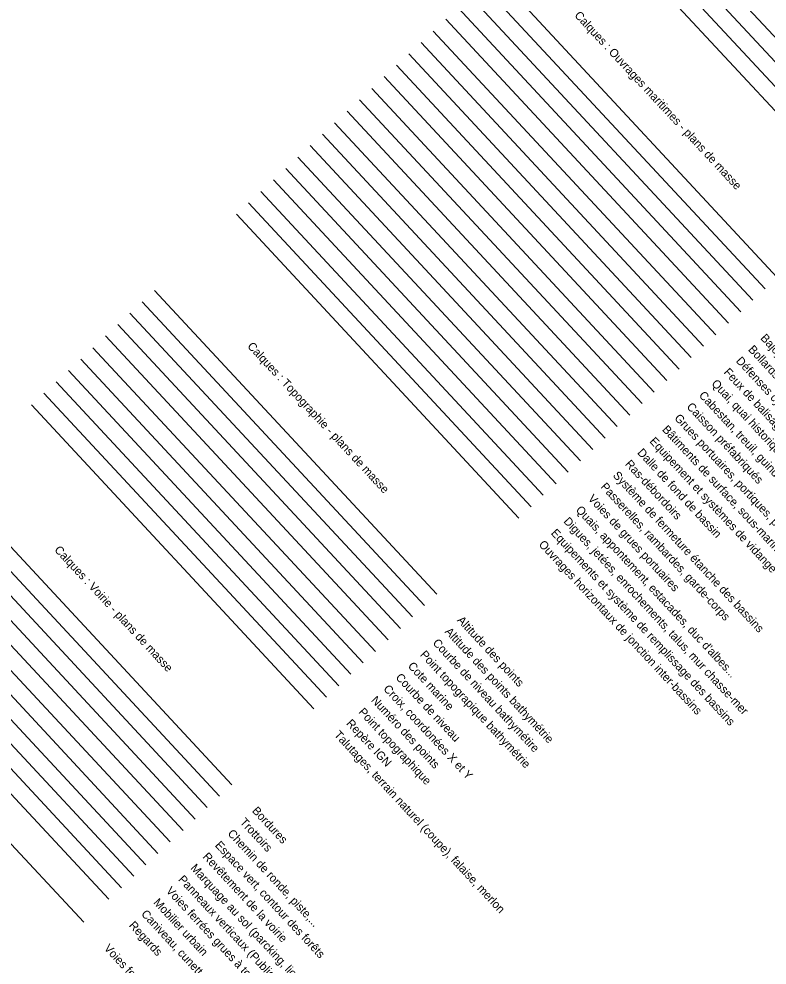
# Model space of a CAD drawing. Extents: x 704383 to 706615, y 7057567 to 7059313.
# Drawn here: x 706408.2 to 706453, y 7057621.5 to 7057678.1 of the extents above; entities that cross this region are included whole.
import ezdxf

# ---------------------------------------------------------------- set-up
doc = ezdxf.new("R2010")
doc.units = 0
for name, color, linetype in [('DH_CADRE -CARTOUCHE', 7, 'Continuous'), ('GEOSID_BATI_AERIEN _POLYGONE', 7, 'Continuous'), ('GEOSID_BATI_AERIEN_NUMERO', 7, 'Continuous'), ('GEOSID_BATI_AERIEN_PRECISION', 7, 'Continuous'), ('GEOSID_SITE_POLYGONE', 7, 'Continuous'), ('OM_BAJOYER', 7, 'Continuous'), ('OM_BATEAU PORTE', 7, 'Continuous'), ('OM_BOLLARDS', 7, 'Continuous'), ('OM_CABESTAN', 7, 'Continuous'), ('OM_CAISSON PREFA', 7, 'Continuous'), ('OM_CONSTRUCTION METAL', 7, 'Continuous'), ('OM_DEFENSE D ACCOSTAGE', 7, 'Continuous'), ('OM_EQUIP DE LEVAGE', 7, 'Continuous'), ('OM_GALERIE REFOULEMENT', 7, 'Continuous'), ('OM_NAVIRE', 7, 'Continuous'), ('OM_OUVRAGES DE PROTECTION', 7, 'Continuous'), ('OM_OUVRAGES D’ACCOSTAGE', 7, 'Continuous'), ('OM_PAL TIR LIER', 7, 'Continuous'), ('OM_PLAGEAGE', 7, 'Continuous'), ('OM_QUAI', 7, 'Continuous'), ('OM_RADIER', 7, 'Continuous'), ('OM_RAS DEBORDOIR', 7, 'Continuous'), ('OM_SIGNAL NAUTIQUE', 7, 'Continuous'), ('OM_SOUBASSEMENT', 7, 'Continuous'), ('OM_STATION DE POMPAGE', 7, 'Continuous'), ('OM_TERRE-PLEINS', 7, 'Continuous'), ('OM_VOIES DE GRUES', 7, 'Continuous'), ('TOPO_ALT POINT', 7, 'Continuous'), ('TOPO_BATHY ALT COURBE NIVEAU', 7, 'Continuous'), ('TOPO_BATHY ALT POINT', 7, 'Continuous'), ('TOPO_BATHYMETRIE', 7, 'Continuous'), ('TOPO_COTE MARINE', 7, 'Continuous'), ('TOPO_COURBE NIVEAU', 7, 'Continuous'), ('TOPO_CROIX COORDONNEE', 7, 'Continuous'), ('TOPO_NUM POINT', 7, 'Continuous'), ('TOPO_POINT', 7, 'Continuous'), ('TOPO_REPERE IGN', 7, 'Continuous'), ('TOPO_TALUS-TERRAIN', 7, 'Continuous'), ('VOIRIE BORDURE', 7, 'Continuous'), ('VOIRIE TROTTOIR', 7, 'Continuous'), ('VOIRIE_CANIVEAU_TECHNIQUE', 7, 'Continuous'), ('VOIRIE_CHEMIN', 7, 'Continuous'), ('VOIRIE_ESPACE VERT', 7, 'Continuous'), ('VOIRIE_MOBILIER_URBAIN', 7, 'Continuous'), ('VOIRIE_REGARD', 7, 'Continuous'), ('VOIRIE_ROUTE_REVETEMENT', 7, 'Continuous'), ('VOIRIE_SIGNAL HORIZON', 7, 'Continuous'), ('VOIRIE_SIGNAL VERTIC', 7, 'Continuous'), ('VOIRIE_VOIES FERREES', 7, 'Continuous'), ('VOIRIE_VOIES GRUE', 7, 'Continuous')]:
    doc.layers.add(name, color=color, linetype=linetype)

msp = doc.modelspace()

# ---------------------------------------------------------------- linework, layer by layer
at = {"layer": 'GEOSID_BATI_AERIEN _POLYGONE'}
msp.add_line((706443.786, 7057687.397), (706460.688, 7057669.229), dxfattribs=at)
at = {"layer": 'GEOSID_BATI_AERIEN_NUMERO'}
msp.add_line((706442.322, 7057686.035), (706459.234, 7057667.856), dxfattribs=at)
at = {"layer": 'GEOSID_BATI_AERIEN_PRECISION'}
msp.add_line((706443.054, 7057686.716), (706459.956, 7057668.548), dxfattribs=at)
at = {"layer": 'GEOSID_SITE_POLYGONE'}
msp.add_line((706441.589, 7057685.353), (706458.502, 7057667.175), dxfattribs=at)
at = {"layer": 'OM_BAJOYER'}
msp.add_line((706434.49, 7057678.759), (706451.402, 7057660.58), dxfattribs=at)
at = {"layer": 'OM_BATEAU PORTE'}
msp.add_line((706425.636, 7057670.522), (706442.549, 7057652.343), dxfattribs=at)
at = {"layer": 'OM_BOLLARDS'}
msp.add_line((706433.758, 7057678.077), (706450.67, 7057659.899), dxfattribs=at)
at = {"layer": 'OM_CABESTAN'}
msp.add_line((706430.806, 7057675.332), (706447.719, 7057657.153), dxfattribs=at)
at = {"layer": 'OM_CAISSON PREFA'}
msp.add_line((706430.074, 7057674.651), (706446.987, 7057656.472), dxfattribs=at)
at = {"layer": 'OM_CONSTRUCTION METAL'}
msp.add_line((706424.904, 7057669.84), (706441.806, 7057651.672), dxfattribs=at)
at = {"layer": 'OM_DEFENSE D ACCOSTAGE'}
msp.add_line((706433.003, 7057677.375), (706449.905, 7057659.207), dxfattribs=at)
at = {"layer": 'OM_EQUIP DE LEVAGE'}
msp.add_line((706429.319, 7057673.948), (706446.222, 7057655.78), dxfattribs=at)
at = {"layer": 'OM_GALERIE REFOULEMENT'}
msp.add_line((706427.855, 7057672.586), (706444.768, 7057654.407), dxfattribs=at)
at = {"layer": 'OM_NAVIRE'}
msp.add_line((706428.587, 7057673.267), (706445.5, 7057655.088), dxfattribs=at)
at = {"layer": 'OM_OUVRAGES DE PROTECTION'}
msp.add_line((706422.685, 7057667.776), (706439.587, 7057649.608), dxfattribs=at)
at = {"layer": 'OM_OUVRAGES D’ACCOSTAGE'}
msp.add_line((706423.44, 7057668.478), (706440.352, 7057650.299), dxfattribs=at)
at = {"layer": 'OM_PAL TIR LIER'}
msp.add_line((706435.222, 7057679.44), (706452.125, 7057661.272), dxfattribs=at)
at = {"layer": 'OM_PLAGEAGE'}
msp.add_line((706436.686, 7057680.802), (706453.589, 7057662.634), dxfattribs=at)
at = {"layer": 'OM_QUAI'}
msp.add_line((706431.539, 7057676.013), (706448.441, 7057657.845), dxfattribs=at)
at = {"layer": 'OM_RADIER'}
msp.add_line((706427.1, 7057671.884), (706444.003, 7057653.716), dxfattribs=at)
at = {"layer": 'OM_RAS DEBORDOIR'}
msp.add_line((706426.368, 7057671.203), (706443.281, 7057653.024), dxfattribs=at)
at = {"layer": 'OM_SIGNAL NAUTIQUE'}
msp.add_line((706432.271, 7057676.694), (706449.173, 7057658.526), dxfattribs=at)
at = {"layer": 'OM_SOUBASSEMENT'}
msp.add_line((706435.954, 7057680.121), (706452.857, 7057661.953), dxfattribs=at)
at = {"layer": 'OM_STATION DE POMPAGE'}
msp.add_line((706421.953, 7057667.095), (706438.865, 7057648.916), dxfattribs=at)
at = {"layer": 'OM_TERRE-PLEINS'}
msp.add_line((706421.22, 7057666.414), (706438.133, 7057648.235), dxfattribs=at)
at = {"layer": 'OM_VOIES DE GRUES'}
msp.add_line((706424.172, 7057669.159), (706441.084, 7057650.98), dxfattribs=at)
at = {"layer": 'TOPO_ALT POINT'}
msp.add_line((706416.317, 7057661.862), (706433.22, 7057643.694), dxfattribs=at)
at = {"layer": 'TOPO_BATHY ALT COURBE NIVEAU'}
msp.add_line((706414.853, 7057660.5), (706431.756, 7057642.332), dxfattribs=at)
at = {"layer": 'TOPO_BATHY ALT POINT'}
msp.add_line((706415.585, 7057661.181), (706432.488, 7057643.013), dxfattribs=at)
at = {"layer": 'TOPO_BATHYMETRIE'}
msp.add_line((706414.121, 7057659.819), (706431.033, 7057641.64), dxfattribs=at)
at = {"layer": 'TOPO_COTE MARINE'}
msp.add_line((706413.389, 7057659.138), (706430.301, 7057640.959), dxfattribs=at)
at = {"layer": 'TOPO_COURBE NIVEAU'}
msp.add_line((706412.634, 7057658.435), (706429.536, 7057640.267), dxfattribs=at)
at = {"layer": 'TOPO_CROIX COORDONNEE'}
msp.add_line((706411.902, 7057657.754), (706428.804, 7057639.586), dxfattribs=at)
at = {"layer": 'TOPO_NUM POINT'}
msp.add_line((706411.17, 7057657.073), (706428.072, 7057638.905), dxfattribs=at)
at = {"layer": 'TOPO_POINT'}
msp.add_line((706410.438, 7057656.392), (706427.35, 7057638.213), dxfattribs=at)
at = {"layer": 'TOPO_REPERE IGN'}
msp.add_line((706409.705, 7057655.711), (706426.618, 7057637.532), dxfattribs=at)
at = {"layer": 'TOPO_TALUS-TERRAIN'}
msp.add_line((706408.951, 7057655.008), (706425.853, 7057636.84), dxfattribs=at)
at = {"layer": 'VOIRIE BORDURE'}
msp.add_line((706404.043, 7057650.462), (706420.945, 7057632.294), dxfattribs=at)
at = {"layer": 'VOIRIE TROTTOIR'}
msp.add_line((706403.31, 7057649.781), (706420.213, 7057631.613), dxfattribs=at)
at = {"layer": 'VOIRIE_CANIVEAU_TECHNIQUE'}
msp.add_line((706397.431, 7057644.311), (706414.343, 7057626.132), dxfattribs=at)
at = {"layer": 'VOIRIE_CHEMIN'}
msp.add_line((706402.578, 7057649.1), (706419.481, 7057630.932), dxfattribs=at)
at = {"layer": 'VOIRIE_ESPACE VERT'}
msp.add_line((706401.846, 7057648.419), (706418.759, 7057630.24), dxfattribs=at)
at = {"layer": 'VOIRIE_MOBILIER_URBAIN'}
msp.add_line((706398.163, 7057644.992), (706415.075, 7057626.813), dxfattribs=at)
at = {"layer": 'VOIRIE_REGARD'}
msp.add_line((706396.676, 7057643.609), (706413.578, 7057625.441), dxfattribs=at)
at = {"layer": 'VOIRIE_ROUTE_REVETEMENT'}
msp.add_line((706401.114, 7057647.738), (706418.026, 7057629.559), dxfattribs=at)
at = {"layer": 'VOIRIE_SIGNAL HORIZON'}
msp.add_line((706400.359, 7057647.036), (706417.262, 7057628.867), dxfattribs=at)
at = {"layer": 'VOIRIE_SIGNAL VERTIC'}
msp.add_line((706399.627, 7057646.354), (706416.529, 7057628.186), dxfattribs=at)
at = {"layer": 'VOIRIE_VOIES FERREES'}
msp.add_line((706395.189, 7057642.225), (706412.081, 7057624.068), dxfattribs=at)
at = {"layer": 'VOIRIE_VOIES GRUE'}
msp.add_line((706398.895, 7057645.673), (706415.797, 7057627.505), dxfattribs=at)

# ---------------------------------------------------------------- texts
at = {"layer": 'DH_CADRE -CARTOUCHE'}
for s, p in [(' Calques : Ouvrages maritimes - plans de masse', (706441.293, 7057678.42)), (' Calques : Topographie - plans de masse', (706421.717, 7057658.628)), (' Calques : Voirie - plans de masse', (706410.169, 7057646.446))]:
    msp.add_text(s, height=0.5, rotation=312.9332, dxfattribs=at).set_placement(p)
at = {"layer": 'OM_BAJOYER'}
msp.add_text('Bajoyers de bassins, parois verticales de quai', height=0.5, rotation=312.9332, dxfattribs=at).set_placement((706452.55, 7057658.979))
at = {"layer": 'OM_BATEAU PORTE'}
msp.add_text('Système de fermeture étanche des bassins', height=0.5, rotation=312.9332, dxfattribs=at).set_placement((706443.719, 7057650.763))
at = {"layer": 'OM_BOLLARDS'}
msp.add_text('Bollards, bittes, organeaux', height=0.5, rotation=312.9332, dxfattribs=at).set_placement((706451.818, 7057658.298))
at = {"layer": 'OM_CABESTAN'}
msp.add_text('Cabestan, treuil, guindeau', height=0.5, rotation=312.9332, dxfattribs=at).set_placement((706448.866, 7057655.552))
at = {"layer": 'OM_CAISSON PREFA'}
msp.add_text('Caisson préfabriqués', height=0.5, rotation=312.9332, dxfattribs=at).set_placement((706448.134, 7057654.871))
at = {"layer": 'OM_CONSTRUCTION METAL'}
msp.add_text('Passerelles, rambardes, garde-corps', height=0.5, rotation=312.9332, dxfattribs=at).set_placement((706442.987, 7057650.082))
at = {"layer": 'OM_DEFENSE D ACCOSTAGE'}
msp.add_text('Défenses cylindriques, pneumatiques, tronconiques', height=0.5, rotation=312.9332, dxfattribs=at).set_placement((706451.086, 7057657.617))
at = {"layer": 'OM_EQUIP DE LEVAGE'}
msp.add_text('Grues portuaires, portiques, palans', height=0.5, rotation=312.9332, dxfattribs=at).set_placement((706447.402, 7057654.19))
at = {"layer": 'OM_GALERIE REFOULEMENT'}
msp.add_text('Equipement et systèmes de vidange des bassins', height=0.5, rotation=312.9332, dxfattribs=at).set_placement((706445.915, 7057652.807))
at = {"layer": 'OM_NAVIRE'}
msp.add_text('Bâtiments de surface, sous-marins, barges', height=0.5, rotation=312.9332, dxfattribs=at).set_placement((706446.67, 7057653.509))
at = {"layer": 'OM_OUVRAGES DE PROTECTION'}
msp.add_text('Digues, jetées, enrochements, talus, mur chasse-mer', height=0.5, rotation=312.9332, dxfattribs=at).set_placement((706440.767, 7057648.018))
at = {"layer": 'OM_OUVRAGES D’ACCOSTAGE'}
msp.add_text("Quais, appontement, estacades, duc d'albes...", height=0.5, rotation=312.9332, dxfattribs=at).set_placement((706441.5, 7057648.699))
at = {"layer": 'OM_QUAI'}
msp.add_text('Quai, quai historique, apparent ou recouvert', height=0.5, rotation=312.9332, dxfattribs=at).set_placement((706449.621, 7057656.255))
at = {"layer": 'OM_RADIER'}
msp.add_text('Dalle de fond de bassin', height=0.5, rotation=312.9332, dxfattribs=at).set_placement((706445.183, 7057652.126))
at = {"layer": 'OM_RAS DEBORDOIR'}
msp.add_text('Ras-débordoirs', height=0.5, rotation=312.9332, dxfattribs=at).set_placement((706444.451, 7057651.444))
at = {"layer": 'OM_SIGNAL NAUTIQUE'}
msp.add_text('Feux de balisage, de navigation, de secours, bouées cardinales', height=0.5, rotation=312.9332, dxfattribs=at).set_placement((706450.353, 7057656.936))
at = {"layer": 'OM_STATION DE POMPAGE'}
msp.add_text('Equipements et système de remplissage des bassins', height=0.5, rotation=312.9332, dxfattribs=at).set_placement((706440.013, 7057647.315))
at = {"layer": 'OM_TERRE-PLEINS'}
msp.add_text('Ouvrages horizontaux de jonction inter-bassins', height=0.5, rotation=312.9332, dxfattribs=at).set_placement((706439.28, 7057646.634))
at = {"layer": 'OM_VOIES DE GRUES'}
msp.add_text('Voies de grues portuaires', height=0.5, rotation=312.9332, dxfattribs=at).set_placement((706442.232, 7057649.38))
at = {"layer": 'TOPO_ALT POINT'}
msp.add_text('Altitude des points', height=0.5, rotation=312.9332, dxfattribs=at).set_placement((706434.4, 7057642.104))
at = {"layer": 'TOPO_BATHY ALT COURBE NIVEAU'}
msp.add_text('Courbe de niveau bathymétire', height=0.5, rotation=312.9332, dxfattribs=at).set_placement((706432.936, 7057640.742))
at = {"layer": 'TOPO_BATHY ALT POINT'}
msp.add_text('Altitude des points bathymétrie', height=0.5, rotation=312.9332, dxfattribs=at).set_placement((706433.668, 7057641.423))
at = {"layer": 'TOPO_BATHYMETRIE'}
msp.add_text('Point topograpique bathymétrie', height=0.5, rotation=312.9332, dxfattribs=at).set_placement((706432.181, 7057640.039))
at = {"layer": 'TOPO_COTE MARINE'}
msp.add_text('Cote marine', height=0.5, rotation=312.9332, dxfattribs=at).set_placement((706431.449, 7057639.358))
at = {"layer": 'TOPO_COURBE NIVEAU'}
msp.add_text('Courbe de niveau', height=0.5, rotation=312.9332, dxfattribs=at).set_placement((706430.717, 7057638.677))
at = {"layer": 'TOPO_CROIX COORDONNEE'}
msp.add_text('Croix, coordonées X et Y', height=0.5, rotation=312.9332, dxfattribs=at).set_placement((706429.985, 7057637.996))
at = {"layer": 'TOPO_NUM POINT'}
msp.add_text('Numéro des points', height=0.5, rotation=312.9332, dxfattribs=at).set_placement((706429.252, 7057637.315))
at = {"layer": 'TOPO_POINT'}
msp.add_text('Point topographique', height=0.5, rotation=312.9332, dxfattribs=at).set_placement((706428.498, 7057636.613))
at = {"layer": 'TOPO_REPERE IGN'}
msp.add_text('Repère IGN', height=0.5, rotation=312.9332, dxfattribs=at).set_placement((706427.765, 7057635.931))
at = {"layer": 'TOPO_TALUS-TERRAIN'}
msp.add_text('Talutages, terrain naturel (coupe), falaise, merlon', height=0.5, rotation=312.9332, dxfattribs=at).set_placement((706427.033, 7057635.25))
at = {"layer": 'VOIRIE BORDURE'}
msp.add_text('Bordures', height=0.5, rotation=312.9332, dxfattribs=at).set_placement((706422.125, 7057630.704))
at = {"layer": 'VOIRIE TROTTOIR'}
msp.add_text('Trottoirs', height=0.5, rotation=312.9332, dxfattribs=at).set_placement((706421.393, 7057630.023))
at = {"layer": 'VOIRIE_CANIVEAU_TECHNIQUE'}
msp.add_text('Caniveau, cunette, fourreau', height=0.5, rotation=312.9332, dxfattribs=at).set_placement((706415.49, 7057624.532))
at = {"layer": 'VOIRIE_CHEMIN'}
msp.add_text('Chemin de ronde, piste,...', height=0.5, rotation=312.9332, dxfattribs=at).set_placement((706420.661, 7057629.342))
at = {"layer": 'VOIRIE_ESPACE VERT'}
msp.add_text('Espace vert, contour des forêts', height=0.5, rotation=312.9332, dxfattribs=at).set_placement((706419.906, 7057628.64))
at = {"layer": 'VOIRIE_MOBILIER_URBAIN'}
msp.add_text('Mobilier urbain', height=0.5, rotation=312.9332, dxfattribs=at).set_placement((706416.223, 7057625.213))
at = {"layer": 'VOIRIE_REGARD'}
msp.add_text('Regards', height=0.5, rotation=312.9332, dxfattribs=at).set_placement((706414.758, 7057623.851))
at = {"layer": 'VOIRIE_ROUTE_REVETEMENT'}
msp.add_text('Revêtement de la voirie', height=0.5, rotation=312.9332, dxfattribs=at).set_placement((706419.174, 7057627.959))
at = {"layer": 'VOIRIE_SIGNAL HORIZON'}
msp.add_text('Marquage au sol (parcking, lignes code de la route)', height=0.5, rotation=312.9332, dxfattribs=at).set_placement((706418.442, 7057627.277))
at = {"layer": 'VOIRIE_SIGNAL VERTIC'}
msp.add_text('Panneaux verticaux (Publicitaire, code de la route)', height=0.5, rotation=312.9332, dxfattribs=at).set_placement((706417.71, 7057626.596))
at = {"layer": 'VOIRIE_VOIES FERREES'}
msp.add_text('Voies ferrées, passage à niveau', height=0.5, rotation=312.9332, dxfattribs=at).set_placement((706413.261, 7057622.478))
at = {"layer": 'VOIRIE_VOIES GRUE'}
msp.add_text('Voies ferrées grues à tour (quai de chargement)', height=0.5, rotation=312.9332, dxfattribs=at).set_placement((706416.978, 7057625.915))

doc.saveas('drawing.dxf')
